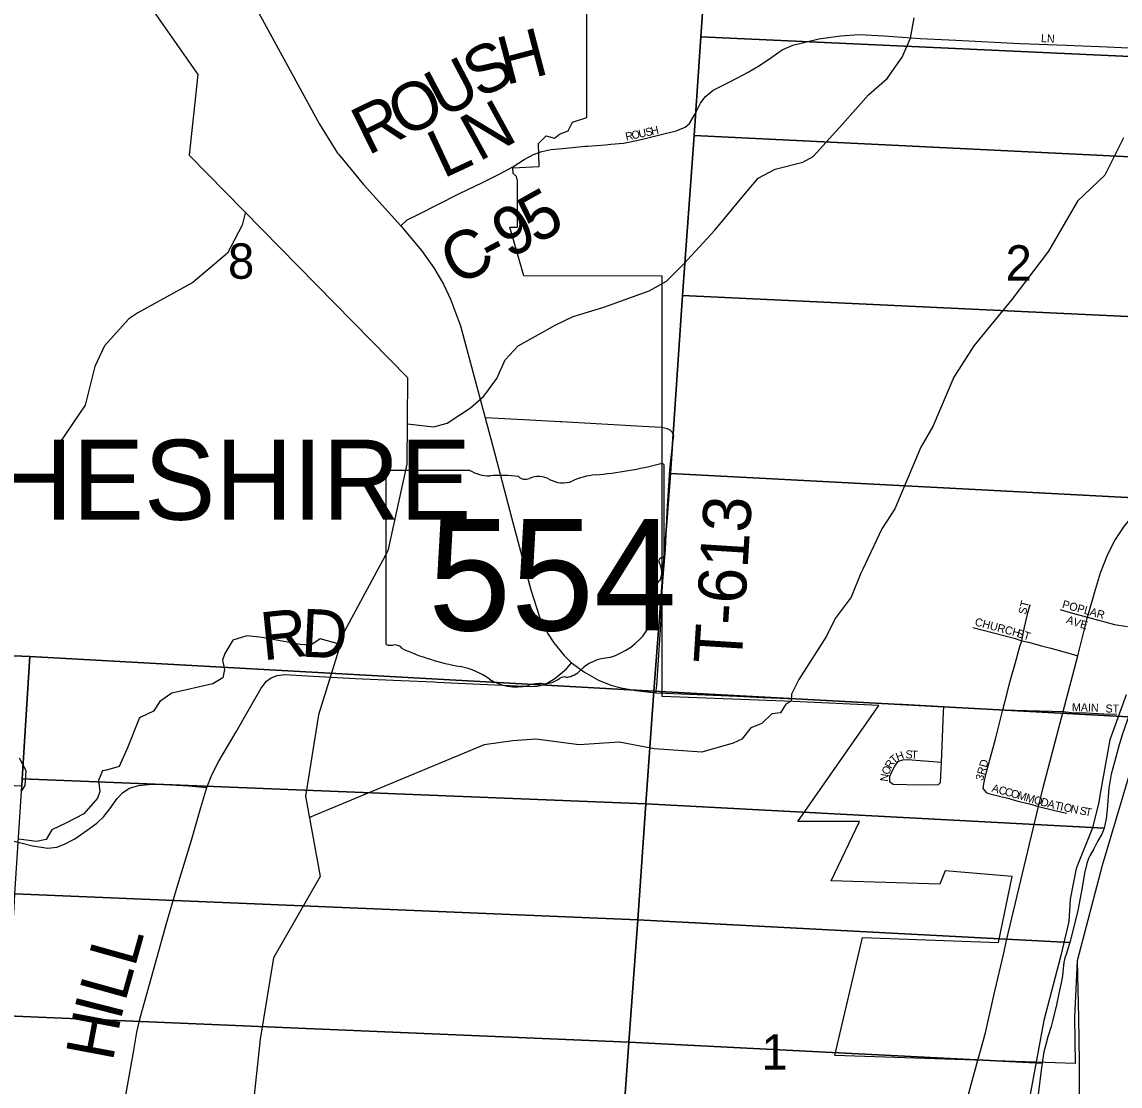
# Model space of a CAD drawing. Extents: x 1878108 to 2183446, y 146837 to 508383.
# Drawn here: x 2072564 to 2079424, y 342011 to 348659 of the extents above; entities that cross this region are included whole.
import ezdxf

# ---------------------------------------------------------------- set-up
doc = ezdxf.new("R2010")
doc.units = 0
for name, color, linetype in [('GM_X_City_Street', 7, 'Continuous'), ('GM_X_City_Street_Text', 7, 'Continuous'), ('GM_X_Corporation', 7, 'Continuous'), ('GM_X_Corporation_Text', 7, 'Continuous'), ('GM_X_County', 7, 'Continuous'), ('GM_X_County_Road', 7, 'Continuous'), ('GM_X_County_Road_Text', 7, 'Continuous'), ('GM_X_Major_River', 7, 'Continuous'), ('GM_X_Minor_River', 7, 'Continuous'), ('GM_X_Section', 7, 'Continuous'), ('GM_X_Section_Text', 7, 'Continuous'), ('GM_X_State_Location', 7, 'Continuous'), ('GM_X_State_Route', 7, 'Continuous'), ('GM_X_State_Shield', 7, 'Continuous'), ('GM_X_Township', 7, 'Continuous'), ('GM_X_Township_Road', 7, 'Continuous'), ('GM_X_Township_Road_Text', 7, 'Continuous')]:
    doc.layers.add(name, color=color, linetype=linetype)

msp = doc.modelspace()

# ---------------------------------------------------------------- linework, layer by layer
at = {"layer": 'GM_X_City_Street'}
for points in [[(2076243.1, 347895.2), (2076321.2, 347902.6), (2076423.5, 347924), (2076548.3, 347953.7), (2076650.5, 347978.7), (2076706.4, 348002.5), (2076733.7, 348025), (2076770.4, 348085.8), (2076803, 348152.7), (2076832.4, 348191.5), (2076882.3, 348233.1), (2076990.5, 348287.8), (2077099.8, 348346), (2077171.2, 348386.4), (2077242.5, 348436.3), (2077312.6, 348485.1), (2077379.2, 348513.6), (2077541.6, 348553.6), (2077678.1, 348573.3), (2077794, 348580.2), (2077949.8, 348573), (2078175.6, 348556.4), (2078398.4, 348545.2), (2078799.4, 348525.5), (2079089.2, 348514.2), (2079342.5, 348504.4), (2079567.6, 348493.4)], [(2078568.7, 343867.6), (2078572.8, 343898.8), (2078587.7, 343966.6), (2078644.7, 344179.5), (2078690.8, 344361.2), (2078719.3, 344465.7), (2078735.5, 344534.8), (2078770.8, 344658.2), (2078796.6, 344757.2), (2078810, 344792), (2078810.5, 344794), (2078826.4, 344877.9), (2078848.1, 344968.8), (2078862.6, 345020.7)], [(2079048.8, 344987.8), (2079119.3, 344967.4), (2079221, 344940.3), (2079389.2, 344895.5), (2079471, 344882.3)], [(2078503.7, 344876.6), (2078633.8, 344842.7), (2078761.3, 344810.1), (2078810, 344792)], [(2078810, 344792), (2078850.8, 344784.3), (2078932.6, 344761.9), (2078990.5, 344746.4), (2079118, 344711.1), (2079160, 344698.9)], [(2078308.9, 344033.1), (2078096.8, 344049.3), (2078064.3, 344048), (2078033.1, 344037.1), (2078014.1, 344010), (2077984.3, 343944.9), (2077984.3, 343915.1), (2078007.3, 343897.5), (2078174.1, 343893.4), (2078289.4, 343894.6), (2078302.5, 343907.5), (2078308.9, 344033.1), (2078320.6, 344347.7), (2078321.9, 344382.9)], [(2079069.1, 344351.8), (2079120.7, 344345), (2079211.3, 344342.3)], [(2079211.3, 344342.3), (2079214.2, 344342.3), (2079322.7, 344336.8), (2079401.4, 344334.1)], [(2078568.7, 343867.6), (2078586.4, 343845.9), (2078609.4, 343837.8), (2078723.3, 343809.3), (2078784.4, 343791.7), (2078857.6, 343774.1), (2078914.5, 343757.8), (2079008.1, 343734.7), (2079089.5, 343715.7)]]:
    msp.add_lwpolyline(points, dxfattribs=at)
at = {"layer": 'GM_X_Corporation'}
msp.add_lwpolyline([(2079662.3, 344563), (2079311.8, 343390.3), (2079155.5, 342792.9), (2079139.5, 342442.2), (2079142.9, 342152.3), (2077641.9, 342203), (2077814.2, 342939.9), (2078663.6, 342907.6), (2078750.7, 343320), (2078332.2, 343355.2), (2078297.5, 343273.2), (2077618.3, 343294.2), (2077795.5, 343664.8), (2077409.9, 343664.8), (2077917.4, 344389.4), (2077381.5, 344414), (2076562.6, 344445.4), (2076563.3, 347071.7), (2075699.3, 347073.7), (2075612.1, 347377.4), (2075658.7, 347376.4), (2075658.7, 347667.1), (2075652.7, 347693.3), (2075631.8, 347712.7), (2075630.3, 347748.4), (2075795.1, 347755.7), (2075790.2, 347899.5), (2075837.7, 347948.9), (2075890.3, 347933.9), (2075921.7, 347959.3), (2075975.5, 347978.7), (2076003.9, 348032.5), (2076092.5, 348062.1), (2076092.6, 348970.1)], dxfattribs=at)
at = {"layer": 'GM_X_County'}
msp.add_lwpolyline([(2079662.3, 344563), (2079311.8, 343390.3), (2079155.5, 342792.9), (2079164.5, 342438.4), (2079167.4, 342161.8), (2079167.4, 341939.3)], dxfattribs=at)
at = {"layer": 'GM_X_County_Road'}
for points in [[(2074930.2, 347384.7), (2074969.7, 347422.4), (2075042.2, 347459.2), (2075162.2, 347518.7), (2075297.6, 347587.1), (2075440.4, 347655.4), (2075549.8, 347711.2), (2075630.6, 347754), (2075701.9, 347799.2), (2075760.2, 347831.3), (2075812.5, 347850.3), (2075867.1, 347863.4), (2075940.5, 347868.3), (2076084.3, 347882.4)], [(2076084.3, 347882.4), (2076096.6, 347883.6), (2076208.3, 347891.9), (2076243.1, 347895.2)], [(2075138.3, 344536.4), (2075157.5, 344535.6), (2075289.9, 344528.7), (2075746, 344506.6), (2075782.4, 344510.2), (2075829.9, 344520.8), (2075893.4, 344557.8), (2075966.3, 344618), (2075997, 344655)], [(2073212.7, 341953.9), (2073259.8, 342223.1), (2073280.6, 342347.9), (2073302.5, 342437.6), (2073401, 342787.8), (2073465.5, 343019.8), (2073530.1, 343240.8), (2073622, 343547.3), (2073682.2, 343751.9), (2073719.7, 343877), (2073750.2, 343955.1), (2073793.5, 344040.7), (2073901.4, 344224.7), (2073994.4, 344385.4), (2074058.9, 344496.4), (2074091.7, 344540.8), (2074121.3, 344560.9), (2074157.2, 344575.7), (2074203.8, 344582.1), (2074348.6, 344573.6), (2074646.3, 344558.3), (2074932.3, 344545.1), (2075138.3, 344536.4)]]:
    msp.add_lwpolyline(points, dxfattribs=at)
at = {"layer": 'GM_X_Major_River'}
msp.add_lwpolyline([(2079461.9, 344456.4), (2079360.6, 344173.5), (2079299.4, 343838.6), (2079291.6, 343784.4), (2079252, 343624), (2079148.6, 343371.1), (2079111.1, 343178.6), (2079103.5, 343040.3), (2079054, 342827.7), (2078947, 342420.5), (2078834.6, 341812.9)], dxfattribs=at)
at = {"layer": 'GM_X_Minor_River'}
for points in [[(2073141, 349348), (2073313.2, 348833.6), (2073663.4, 348331.8), (2073609.4, 347826.6), (2074973.3, 346438.2)], [(2074970.4, 346148.9), (2075137.8, 346129.9), (2075219.5, 346152.3), (2075366.9, 346249.2), (2075448.4, 346321.8), (2075529.7, 346432.3), (2075583.1, 346548.8), (2075664.6, 346635.4), (2075899.6, 346766.8), (2076007.2, 346819.4), (2076198.7, 346876.5), (2076481.8, 346980), (2076591.3, 347040.7), (2076686.7, 347135.3), (2076698.7, 347147.4), (2076891.4, 347358.8), (2077062.1, 347564), (2077163.4, 347682.7), (2077269, 347739.4), (2077442.5, 347784.3), (2077506.3, 347818.7), (2077689, 348020), (2077851.9, 348205.1), (2077969.3, 348305.9), (2078062.5, 348438.6), (2078113.8, 348557.1), (2078137.2, 348685.5)], [(2079444.2, 347935.3), (2079329, 347702.9), (2079158, 347539), (2078976.4, 347226.6), (2078746.8, 346926.4), (2078511.2, 346636.3), (2078386.1, 346440.1), (2078254.6, 346131.5), (2078180, 346003.4), (2078016, 345616.6), (2077935.4, 345492.5), (2077816.1, 345240.1), (2077804, 345216.1), (2077743.3, 345065.8), (2077644.5, 344931.7), (2077590, 344821.6), (2077416.5, 344551.3), (2077372.1, 344459.2), (2077369.9, 344415.1), (2077335.7, 344397.1), (2077303.5, 344343.1), (2077249.4, 344337.3), (2077185, 344277.4), (2077116.8, 344249.6), (2077060.4, 344179.6), (2077006.2, 344153.8), (2076811.6, 344096.4), (2076513.2, 344117.8), (2076493.2, 344122), (2076295, 344159), (2076044.6, 344144), (2075774.3, 344179.4), (2075630, 344168), (2075451.6, 344142.7), (2074360.1, 343689.2), (2074370.2, 343692.5)], [(2073959.6, 347474), (2073939, 347390.4), (2073847, 347214.9), (2073630.8, 347031.9), (2073288.5, 346841.5), (2073230.9, 346804.7), (2073078.6, 346636.5), (2073020.1, 346507.5), (2072958.9, 346266.2), (2072801.4, 346031.8)], [(2074973.3, 346438.2), (2074967.9, 345897.6), (2074850, 345354.2), (2074579.8, 344852.5), (2074415.7, 344331.1), (2074335.7, 343822), (2074427.7, 343321.5), (2074135.5, 342811.8), (2074051.5, 342304.8), (2073997.4, 341797.8), (2074131.5, 341293.5), (2074317.7, 340771.4), (2074037.5, 340267.7), (2073534.9, 340330.1), (2073244.7, 339826.4), (2073748.2, 339517.6), (2073368, 339017.5), (2073674.2, 338513.8), (2073784.2, 338005.3), (2073868.3, 337504.7)], [(2074553.6, 344769.3), (2074427.2, 344806), (2074367.5, 344765.7), (2074301.6, 344769.4), (2074063.7, 344814.3), (2073969.7, 344823.8), (2073882, 344797.4), (2073830.5, 344713), (2073816.7, 344672.8), (2073829, 344612.8), (2073819.2, 344562.7), (2073755.5, 344524.3), (2073500.1, 344466.9), (2073424.5, 344414.5), (2073384.8, 344354.2), (2073307.1, 344315.7), (2073295.2, 344307.7), (2073222.2, 344125), (2073170.8, 344008.6), (2073093, 343984.1), (2073067.1, 343980), (2073041.4, 343919.8), (2073049.7, 343851.7), (2073036, 343809.6), (2072950.5, 343713), (2072843, 343656.4), (2072751.3, 343611.9), (2072715.6, 343551.6), (2072653.8, 343539.3), (2072543.8, 343554.8)], [(2072558.4, 343849.3), (2072584.2, 343889.5), (2072589.7, 343981.7), (2072549.4, 344059.6)]]:
    msp.add_lwpolyline(points, dxfattribs=at)
at = {"layer": 'GM_X_Section'}
for points in [[(2071630.5, 349983.6), (2076880.8, 349683.9), (2076866.7, 349473.1), (2076805.5, 348566.4), (2076763.7, 347950.2), (2076689.4, 346949.7), (2076616.1, 345838.6), (2076512.2, 344478.8), (2072614, 344694.3), (2071013.5, 344761.7), (2071063, 345547.6), (2071115.7, 346380.1), (2071171.8, 347265.2), (2071227.3, 348141.2), (2071283.3, 349025.1), (2071330.9, 349777.5), (2071344.9, 349998.6)], [(2076866.7, 349473.1), (2082378.7, 349266.2), (2082364.3, 349229.8), (2082334.6, 349175.6), (2082290.9, 349107.4), (2082229.3, 349011.1), (2082191.6, 348950.9), (2082155.9, 348888.7), (2082130.2, 348828.6), (2082108.4, 348784.4), (2082076.7, 348730.3), (2082039, 348668.1), (2081951.6, 348529.6), (2081925.8, 348487.5), (2081886.1, 348419.3), (2081847.9, 348335.3), (2076805.5, 348566.4)], [(2081847.9, 348335.3), (2081838.6, 348315), (2081777.2, 348186.7), (2081733.6, 348102.4), (2081690, 348030.2), (2081632.4, 347933.9), (2081541.1, 347793.4), (2081489.5, 347718.3), (2076763.7, 347950.2), (2076805.5, 348566.4)], [(2076763.7, 347950.2), (2081489.5, 347718.3), (2081419.9, 347616.8), (2081318.5, 347474.3), (2081181.4, 347285.5), (2081100, 347171.1), (2081086.1, 347147), (2081074.2, 347124.9), (2081064.3, 347108.9), (2081044.4, 347086.8), (2081022.5, 347062.7), (2080966.8, 346998.4), (2080891.2, 346900), (2080794.3, 346757.7), (2076689.4, 346949.7)], [(2076616.1, 345838.6), (2080144.2, 345652.6), (2080027.8, 345493.4), (2079958.3, 345391.1), (2079940.5, 345359), (2079940.5, 345345), (2079938.6, 345327), (2079936.7, 345313), (2079930.8, 345294.9), (2079916.9, 345264.8), (2079899.1, 345234.7), (2079875.2, 345194.6), (2079853.4, 345162.5), (2079821.6, 345122.3), (2079789.8, 345072.2), (2079754.1, 345010), (2079718.4, 344941.8), (2079690.7, 344881.6), (2079645.2, 344767.4), (2079570.2, 344577), (2079503, 344390.6), (2079497.3, 344375), (2079476.4, 344317.9), (2076512.2, 344478.8)], [(2071013.5, 344761.7), (2072614, 344694.3), (2072565.4, 343930.7), (2072562.5, 343884.5), (2070965.8, 343958.4)], [(2072614, 344694.3), (2076512.2, 344478.8), (2076462, 343774.7), (2072565.4, 343930.7)], [(2076512.2, 344478.8), (2079476.4, 344317.9), (2079465.5, 344288.4), (2079435.9, 344206.2), (2079414.3, 344128.1), (2079388.7, 344033.9), (2079369.1, 343959.8), (2079353.5, 343871.7), (2079342.2, 343739.6), (2079336.5, 343681.6), (2079324.7, 343622.2), (2076462, 343774.7)], [(2072562.5, 343884.5), (2072565.4, 343930.7), (2076462, 343774.7), (2076410.5, 343050.4), (2072519.6, 343211.3)], [(2079324.7, 343622.2), (2079318.8, 343605.5), (2079310.9, 343585.5), (2079283.1, 343539.3), (2079259.4, 343493.2), (2079237.5, 343453.1), (2079225.6, 343433), (2079215.8, 343400.9), (2079202.1, 343340.9), (2079186.5, 343252.8), (2079159.2, 343108.6), (2079127.8, 342980.4), (2079109.4, 342908.5), (2076410.5, 343050.4), (2076462, 343774.7)], [(2072514.2, 343126.8), (2072519.6, 343211.3), (2076410.5, 343050.4), (2076356, 342285.1), (2072471.2, 342451)], [(2076410.5, 343050.4), (2079109.4, 342908.5), (2079098.3, 342868.2), (2079086.5, 342832.2), (2079078.6, 342812.1), (2079072.7, 342784.1), (2079068.9, 342746), (2079065.1, 342700), (2079053.4, 342645.9), (2079041.7, 342589.9), (2079026, 342519.8), (2079004.5, 342425.7), (2078992.7, 342383.6), (2078973, 342319.5), (2078957.2, 342263.4), (2078947.4, 342225.3), (2078939.7, 342171.3), (2078936.9, 342154.1), (2076356, 342285.1)], [(2072466.8, 342382.3), (2072471.2, 342451), (2076356, 342285.1), (2076304, 341554.2), (2072420.5, 341706.8)], [(2078936.9, 342154.1), (2078930, 342111.2), (2078910.8, 341941.1), (2078891.5, 341790.9), (2078876, 341692.8), (2078860.4, 341616.7), (2078815.1, 341449.9), (2076304, 341554.2), (2076356, 342285.1)]]:
    msp.add_lwpolyline(points, close=True, dxfattribs=at)
msp.add_lwpolyline([(2080144.2, 345652.6), (2076616.1, 345838.6), (2076689.4, 346949.7), (2080794.3, 346757.7)], dxfattribs=at)
at = {"layer": 'GM_X_State_Route'}
for points in [[(2073991.5, 348812.6), (2074127, 348562.1), (2074274.9, 348291.8), (2074422.8, 348021.5), (2074535.8, 347839.6), (2074543.3, 347830.5)], [(2074543.3, 347830.5), (2074697.4, 347644.7), (2074930.2, 347384.7), (2075058.8, 347231), (2075137.3, 347122.8), (2075196.7, 347020.6), (2075241.9, 346927.9), (2075302.5, 346761.4), (2075456.7, 346186.1), (2075517, 345960.8), (2075621.7, 345564.3), (2075742.4, 345111.9), (2075799.1, 344935.6), (2075847.9, 344841.1), (2075886, 344780.9), (2075950.5, 344700.5), (2075997, 344655), (2076077.4, 344597.9), (2076165.1, 344548.2), (2076243.4, 344516.5), (2076306.8, 344499.6), (2076399.8, 344481.6), (2076524.5, 344468.9)], [(2079264.5, 345092.4), (2079301, 345216.9), (2079347.1, 345333.6), (2079391.9, 345420.4), (2079448.8, 345507.1), (2079520.7, 345593.9), (2079579, 345657.7), (2079640.2, 345713)], [(2079069.1, 344351.8), (2079160, 344698.9), (2079221, 344940.3), (2079257.6, 345069.1), (2079264.5, 345092.4)], [(2076524.5, 344468.9), (2076581.3, 344465.9), (2077031.2, 344446.3), (2077192.2, 344439.5)], [(2077192.2, 344439.5), (2077397.7, 344430.9)], [(2077397.7, 344430.9), (2077398.5, 344430.9), (2077530.3, 344423.9), (2077911.2, 344404.2)], [(2077911.2, 344404.2), (2078065.2, 344396.2)], [(2078065.2, 344396.2), (2078321.9, 344382.9), (2078690.8, 344361.2), (2079069.1, 344351.8)], [(2078927.1, 343807.4), (2078944.4, 343875.8), (2079069.1, 344351.8)], [(2078695, 342833.5), (2078715.2, 342919.7), (2078914.5, 343757.8), (2078927.1, 343807.4)], [(2078635, 342576.5), (2078643.3, 342613.2), (2078695, 342833.5)], [(2078548, 342217.5), (2078582.3, 342344.7), (2078635, 342576.5)], [(2077811.1, 339961.9), (2077878.5, 340131.6), (2078031.7, 340572.3), (2078132.1, 340872), (2078204, 341063.2), (2078316.5, 341390.1), (2078328.7, 341470.1), (2078353.1, 341552.8), (2078458.9, 341891.8), (2078536.2, 342173.9), (2078548, 342217.5)]]:
    msp.add_lwpolyline(points, dxfattribs=at)
at = {"layer": 'GM_X_State_Shield'}
for p, q in [((2076576.2, 345331.5), (2076576.2, 345884.3)), ((2074836, 345839.9), (2074836, 344783.3)), ((2075362.7, 345858.1), (2074853.1, 345858.1)), ((2076576, 345331.7), (2076576.2, 345331.5))]:
    msp.add_line(p, q, dxfattribs=at)
for centre, major_axis, start_param, end_param in [((2075956.3, 347298.6), (1845.5, 0), 4.814394, 5.042369), ((2076556.9, 345886.6), (19.4, 0), 6.141152, 7.989035), ((2074855.9, 345842.1), (20.2, 0), 1.712693, 3.28349), ((2075484.1, 345980.7), (195.5, 0), 4.042523, 4.731795), ((2075548.9, 345264.9), (702, 0), 1.404758, 1.657858), ((2075708.3, 345847.6), (56.4, 0), 3.836095, 5.185415), ((2075791.1, 345725.5), (117.3, 0), 0.950623, 2.079405), ((2075942.5, 345893), (141.1, 0), 4.081561, 5.145723), ((2076191.7, 345535.3), (371.3, 0), 1.699011, 2.107814), ((2076555.5, 345329.4), (20.7, 0), 5.05454, 6.418171), ((2076571.7, 345290.9), (30, 0), 1.883978, 3.671073), ((2076380.9, 345221.1), (180, 0), 5.934695, 6.695948), ((2076645.6, 345100.2), (130.9, 0), 2.387724, 3.262537), ((2076059.7, 345029.9), (461.6, 0), 5.101752, 6.440018), ((2074856.1, 344780.9), (20.3, 0), 3.00124, 4.508301), ((2074890.9, 344722.3), (56, 0), 0.519207, 1.627899), ((2074859.2, 344889), (155.2, 0), 4.665946, 4.897461), ((2075597.5, 345671.6), (1332.7, 0), 4.195997, 4.488961), ((2075200.2, 344308.6), (417, 0), 0.823519, 1.323587), ((2076254.3, 344486.6), (252.8, 0), 1.647645, 2.488434), ((2075950.9, 344535.6), (39.7, 0), 1.147584, 2.315152), ((2075934, 344680.9), (149.1, 0), 4.937069, 5.64225), ((2075651.2, 344717.1), (264.6, 0), 4.026481, 4.996735), ((2075804.1, 344351.7), (217.4, 0), 1.495662, 1.94098), ((2075823.4, 344637.9), (141, 0), 4.691044, 5.507374)]:
    msp.add_ellipse(centre, major_axis=major_axis, ratio=0.8, start_param=start_param, end_param=end_param, dxfattribs=at)
at = {"layer": 'GM_X_Township'}
msp.add_lwpolyline([(2079662.3, 344563), (2079311.8, 343390.3), (2079155.5, 342792.9), (2079164.5, 342438.4), (2079167.4, 342161.8), (2079167.4, 341939.3)], dxfattribs=at)
at = {"layer": 'GM_X_Township_Road'}
for points in [[(2075933.8, 346161.2), (2075925.1, 346161.7), (2075735.8, 346172.3), (2075499, 346183.9), (2075456.7, 346186.1)], [(2076618.3, 346105.5), (2076616.6, 346107.8), (2076597.6, 346118.4), (2076559.5, 346124.7), (2076441.1, 346132.1), (2075933.8, 346161.2)], [(2076524.5, 344468.9), (2076529.4, 344513.6), (2076557.4, 344925.7), (2076561.6, 345068.7), (2076567.2, 345162.6), (2076584.1, 345364.5), (2076595.3, 345601.4), (2076610.7, 345862.1), (2076630.3, 346034.6), (2076635.6, 346071.9), (2076627.2, 346093.6), (2076618.3, 346105.5)], [(2072458.1, 343556.5), (2072565.8, 343529), (2072630.4, 343512.1), (2072725.6, 343498.3), (2072781.6, 343504.7), (2072830.3, 343521.6), (2072893.7, 343556.5), (2072970.9, 343609.3), (2073031.2, 343653.7), (2073074.5, 343695), (2073112.6, 343742.6), (2073158.1, 343808.1), (2073194, 343845.1), (2073236.3, 343871.6), (2073291.3, 343888.5), (2073351.6, 343895.9), (2073418.9, 343897), (2073492.2, 343892.7), (2073604.3, 343886.4), (2073719.7, 343877)]]:
    msp.add_lwpolyline(points, dxfattribs=at)

# ---------------------------------------------------------------- texts
at = {"layer": 'GM_X_City_Street_Text'}
for s, rotation, p in [('LN', 356.98902, (2078928.8, 348533.7)), ('U', 12.09018, (2076420.9, 347935)), ('S', 12.11187, (2076463.9, 347944.2)), ('H', 12.81353, (2076499, 347951.8)), ('R', 12.08628, (2076339.1, 347917.5)), ('O', 12.09018, (2076377.9, 347925.8)), ('ST', 75.97018, (2078835.6, 344953.8)), ('POPLAR', 344.65065, (2079058.4, 345000.2)), ('CHURCH', 345.00544, (2078512.7, 344890.2)), ('A', 340.92239, (2079083.6, 344905.5)), ('V', 341.43621, (2079125.7, 344890.9)), ('E', 344.67219, (2079170.3, 344876)), ('ST', 342.64131, (2078772.7, 344819.7)), ('MAIN', 358.49332, (2079122.1, 344353.7)), ('ST', 0.00001, (2079333.1, 344344.9)), ('T', 40.82354, (2078011.1, 344021.5)), ('H', 20.70953, (2078033.7, 344042.1)), ('S', 358.5242, (2078082.9, 344058.8)), ('T', 357.73232, (2078117.9, 344057.9)), ('R', 59.88164, (2077994, 343990.6)), ('3RD', 74.35644, (2078567.2, 343915.6)), ('N', 82.39235, (2077972.8, 343911.3)), ('O', 67.17164, (2077977.7, 343951.6)), ('A', 344.33081, (2078618.6, 343851.7)), ('C', 344.30817, (2078661, 343839.8)), ('C', 344.3241, (2078699.1, 343829.1)), ('O', 344.30977, (2078737.2, 343818.4)), ('M', 344.33053, (2078779.6, 343806.5)), ('M', 344.32478, (2078830.5, 343792.2)), ('O', 344.30977, (2078881.3, 343777.9)), ('D', 344.3315, (2078923.7, 343766)), ('A', 344.94584, (2078966.6, 343754)), ('T', 347.91012, (2079011.9, 343741.9)), ('I', 348.63124, (2079046.9, 343734.4)), ('O', 348.69089, (2079068.6, 343730)), ('N', 348.69435, (2079111.7, 343721.4)), ('S', 348.69543, (2079167.8, 343710.2)), ('T', 348.69419, (2079202.3, 343703.3))]:
    msp.add_text(s, height=50, rotation=rotation, dxfattribs=at).set_placement(p)
at = {"layer": 'GM_X_Corporation_Text'}
msp.add_text('CHESHIRE', height=500, rotation=0.00001, dxfattribs=at).set_placement((2071914.7, 345549.3))
at = {"layer": 'GM_X_County_Road_Text'}
for s, rotation, p in [('H', 14.69888, (2075585.2, 348263.9)), ('S', 27.71472, (2075422.8, 348176.2)), ('U', 27.81504, (2075189.4, 348053.1)), ('O', 26.4054, (2074945.8, 347932)), ('R', 26.40796, (2074725.1, 347822.5)), ('N', 28.80709, (2075417.7, 347783.6)), ('L', 25.02776, (2075195.4, 347679.1)), ('5', 29.3515, (2075775.7, 347266.4)), ('9', 27.80945, (2075605.8, 347176.6)), ('C', 27.79215, (2075281.3, 347005.6)), ('-', 27.7945, (2075497.7, 347119.6)), ('R', 5.7704, (2074069.4, 344670.5)), ('D', 357.19399, (2074302.7, 344694.9)), ('L', 74.32951, (2073268.7, 342747.6)), ('L', 74.48138, (2073208.7, 342531.6)), ('I', 75.74792, (2073178.8, 342413.8)), ('H', 79.29016, (2073130.8, 342159.2))]:
    msp.add_text(s, height=300, rotation=rotation, dxfattribs=at).set_placement(p)
at = {"layer": 'GM_X_Section_Text'}
for s, p in [('8', (2073850.7, 347055)), ('2', (2078708.3, 347043.4)), ('1', (2077183.7, 342113.8))]:
    msp.add_text(s, height=221, rotation=0.00001, dxfattribs=at).set_placement(p)
at = {"layer": 'GM_X_State_Location'}
for s in ['s', 'r']:
    msp.add_text(s, height=1, dxfattribs=at).set_placement((2075686.5, 345241.3))
msp.add_text('554', height=1, rotation=0.00001, dxfattribs=at).set_placement((2075333.5, 345168.6))
at = {"layer": 'GM_X_State_Shield'}
msp.add_text('554', height=696.1, dxfattribs=at).set_placement((2075101.7, 344857.8))
at = {"layer": 'GM_X_Township_Road_Text'}
msp.add_text('T-613', height=300, rotation=86.38902, dxfattribs=at).set_placement((2077058.7, 344641.2))

doc.saveas('drawing.dxf')
